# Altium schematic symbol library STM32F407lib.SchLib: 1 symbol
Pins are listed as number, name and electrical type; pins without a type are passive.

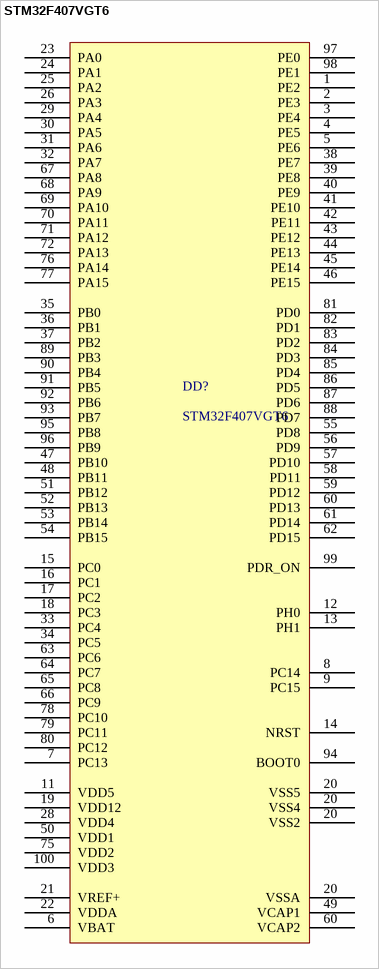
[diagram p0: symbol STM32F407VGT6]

## STM32F407VGT6
designator DD?
STM32F407VGT6 ARM-Cortex-M4F microcontroller
pins: 1 PE2, 2 PE3, 3 PE4, 4 PE5, 5 PE6, 6 VBAT, 7 PC13, 8 PC14, 9 PC15, 11 VDD5, 12 PH0, 13 PH1, 14 NRST, 15 PC0, 16 PC1, 17 PC2, 18 PC3, 19 VDD12, 20 VSSA, 20 VSS5, 20 VSS4, 20 VSS2, 21 VREF+, 22 VDDA, 23 PA0, 24 PA1, 25 PA2, 26 PA3, 28 VDD4, 29 PA4, 30 PA5, 31 PA6, 32 PA7, 33 PC4, 34 PC5, 35 PB0, 36 PB1, 37 PB2, 38 PE7, 39 PE8, 40 PE9, 41 PE10, 42 PE11, 43 PE12, 44 PE13, 45 PE14, 46 PE15, 47 PB10, 48 PB11, 49 VCAP1, 50 VDD1, 51 PB12, 52 PB13, 53 PB14, 54 PB15, 55 PD8, 56 PD9, 57 PD10, 58 PD11, 59 PD12, 60 PD13, 60 VCAP2, 61 PD14, 62 PD15, 63 PC6, 64 PC7, 65 PC8, 66 PC9, 67 PA8, 68 PA9, 69 PA10, 70 PA11, 71 PA12, 72 PA13, 75 VDD2, 76 PA14, 77 PA15, 78 PC10, 79 PC11, 80 PC12, 81 PD0, 82 PD1, 83 PD2, 84 PD3, 85 PD4, 86 PD5, 87 PD6, 88 PD7, 89 PB3, 90 PB4, 91 PB5, 92 PB6, 93 PB7, 94 BOOT0, 95 PB8, 96 PB9, 97 PE0, 98 PE1, 99 PDR_ON, 100 VDD3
